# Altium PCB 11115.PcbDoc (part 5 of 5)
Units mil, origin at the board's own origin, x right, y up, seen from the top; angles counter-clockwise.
Board outline 4800 x 3500.1 mil, 4 copper layers (Top Layer, Layer 2, Layer 3, Bottom Layer), stack 61.6 mil thick; 316 components, 224 nets, 954 pads, 623 vias.
Unrouted connection lines stored in the file: 268.
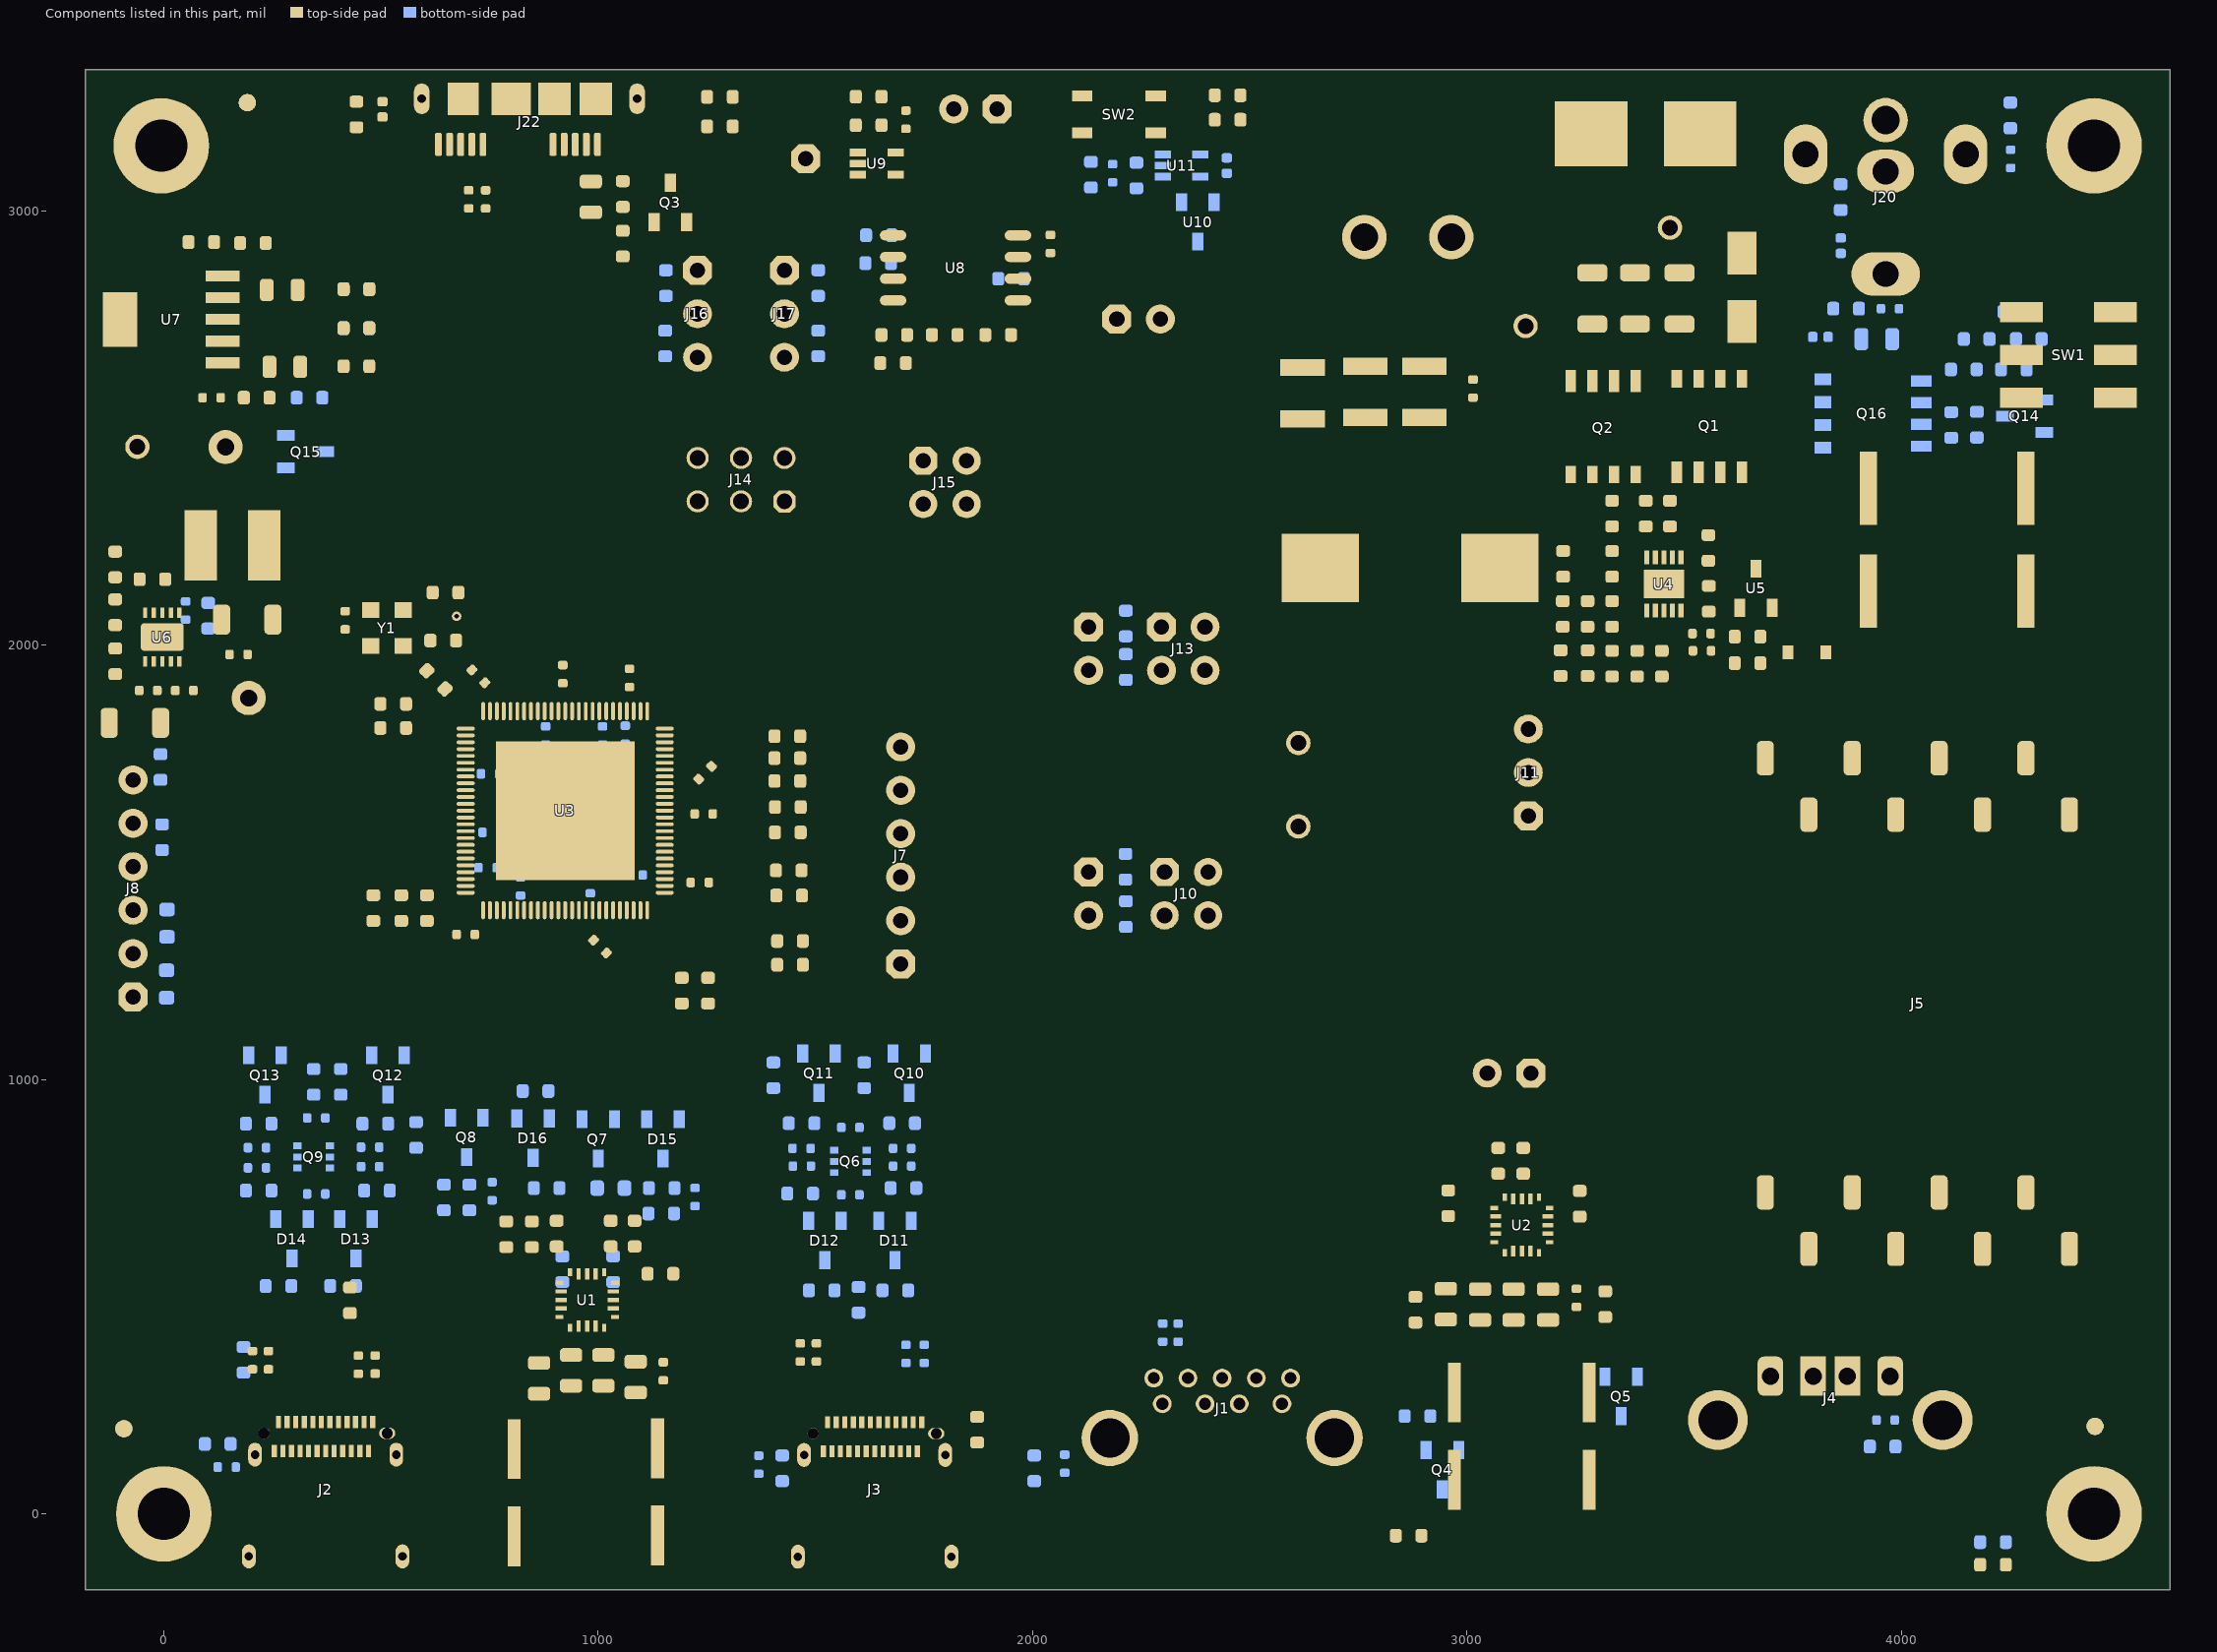
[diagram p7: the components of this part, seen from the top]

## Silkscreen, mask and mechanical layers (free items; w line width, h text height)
Top Overlay:
  circle w10: c1975.4,3285.12 r12
  circle w10: c7.55,1142.26 r12
  circle w10: c3197.78,1070.01 r12
  circle w10: c72.56,2065.34 r12
  circle w10: c677.47,1862.67 r12
  circle w10: c2244.15,1534.48 r12
  circle w10: c2068.15,1534.48 r12
  circle w10: c1764.55,1218.14 r12
  circle w10: c2239.15,2094.65 r12
  circle w10: c2135.4,2690.12 r12
  circle w10: c1689.34,2477.36 r12
  circle w10: c1486.44,2273.42 r12
  circle w10: c1355.4,2909.06 r12
  circle w10: c2072.4,2094.65 r12
  circle w10: c1160.4,2910.12 r12
  circle w10: c3209.18,1557.84 r18.03
  region: 74.15,425 74.15,1110 -130.85,1110 -130.85,425
  lines w8: -0.78,1505.87 41.96,1505.87 41.96,1572.5 -0.78,1572.5 ; 0.82,1196.05 43.56,1196.05 43.56,1262.68 0.82,1262.68 ; 0.82,1319.94 43.56,1319.94 43.56,1386.57 0.82,1386.57 ; 1.16,1607.5 43.89,1607.5 43.89,1674.13 1.16,1674.13 ; 651.44,2760 1170.72,2760 1172.66,2758.06 1172.66,2520.88 1160.4,2520.88 651.44,2520.88 651.44,2835 1024.15,2835 ; 1019.15,2835 1173.85,2835 ; 1484.08,2607.22 1546.3,2545 1948.98,2545 1948.98,2273.42 2558.37,2273.42 ; 1664.15,2200 1948.98,2200 1948.98,2191.99 1948.98,2060.17 1664.15,2060.17 1664.15,2240.63 1696.15,2272.64 ; 1806.56,2060.17 1806.56,2200 ; 1948.98,2524.42 1948.98,2585 1951.06,2587.09 2472.86,2587.09 2472.86,2385 2558.37,2385 ; 2251.79,1807.09 2251.79,1607.09 2321.15,1607.09 2378.26,1607.09 2447.62,1607.09 2447.62,1817.26 ; 2254.69,1255.92 2254.69,1023.72 2450.52,1023.72 2450.52,1266.09 ; 2819.15,1725 3009.15,1725 3008.05,1726.1 3008.05,1895 ; 3008.05,1889.92 3305.23,1889.92 3345.82,1889.92 3360.9,1905 3359.15,1905 ; 3222.15,2271 3285.15,2271 3310.15,2246 3435.15,2246 3440.15,2251 ; 3510.79,1825 3594.98,1825 3602.85,1825 3602.85,1918.44 3564.72,1957.21
  lines w10: 2727.75,2796.73 2799.75,2796.73 ; 2921.57,2795 2993.57,2795 ; 2958.42,2755 2958.42,2827
  lines w11: -155.85,2360 -155.85,2118.13 -146.46,2108.73 -146.46,2109.4
  text "\"SPI\"" at 1468.26,3265 h60
  text "\"VBUS\"" at 1331.53,3204.56 h60
  text "HOLD" at 1824.15,3109.13 h60
  text "RESET" at 2294.15,3090.63 h60
  text "GND" at 1319.15,3052.2 h60
  text "SST26VF016B" at 1745.61,3006.91 h100
  text "DC_IN" at 2581.75,2979.22 h120 r90
  text "DC_IN" at 3236.59,2941.73 h75
  text "12Vin" at 4237.26,2916.49 h120
  text "J6" at 679.97,2853.56 h60
  text "\"5V\"" at 521.7,2800.41 h60
  text "BATT CHRGING" at 689.47,2775 h60
  text "\"3V3\"" at 513.34,2714.67 h60
  text "(1-2)" at 679.97,2705 h60
  text "ALL PORTS DISABLED" at 672.67,2649.73 h60
  text "RESET" at 2179.46,2640.07 h60
  text "GND" at 3080,2635 h60
  text "\"1V1\"" at 513.34,2626.37 h60
  text "(2-3)" at 683.51,2599.35 h60
  text "ALL PORTS ENABLED" at 670.76,2541.12 h60
  text "Non-Removable" at 2072.4,2520.88 h60
  text "J7" at 1979.15,2520 h60
  text "◄ ON   OFF ►" at 4604.15,2500 h70 r90
  text "SELECT" at 2072.4,2465.55 h60
  text "3V3" at 207.7,2415 h60
  text "6" at 1123.32,2415 h60
  text "4" at 1505.35,2410 h60
  text "(1-2)" at 1964.15,2375 h60
  text "ALL REMOVABLE" at 2076,2375 h60
  text "GND" at -9.82,2369.83 h60
  text "(2-3)" at 1964.15,2310 h60
  text "ALL NON-REMOVABLE" at 2076,2310 h60
  text "3" at 1123.32,2305 h60
  text "STRAP" at 1132.45,2190.4 h60
  text "SPI" at 1389.99,2190.4 h60
  text "[1-2]" at 1373.85,2141.88 h60
  text "PF24" at 1689.34,2141.88 h60
  text "PF22" at 1824.15,2141.88 h60
  text "[2-3]" at 1160.4,2131.54 h60
  text "CLK/PF31" at 2244.78,2120 h60
  text "[4-5]" at 1373.85,2080.12 h60
  text "PF25" at 1692.09,2080.12 h60
  text "PF21" at 1824.15,2080.12 h60
  text "[5-6]" at 1160.4,2073.33 h60
  text "P/U ENABLE" at 2035,1855 h60 r90
  text "VCORE" at 264.64,1835.67 h60
  text "DATA/PF30" at 2244.15,1830 h60
  text "5V" at 4302.22,1825 h60 r90
  text "SCL" at 4107.22,1815 h60 r90
  text "DAT" at 4207.22,1815 h60 r90
  text "GND" at 4412.7,1815 h60 r90
  text "SPR1" at 3707.22,1795 h60 r90
  text "SPR2" at 3905.94,1795 h60 r90
  text "SPR3" at 4007.05,1795 h60 r90
  text "MIC DET" at 3805.22,1790 h55 r90
  text "SPARE3" at 3222.15,1780 h60
  text "PF29" at 1769.15,1745 h60
  text "5V" at 2687.53,1721.69 h60
  text "USB7252" at 335,1695.42 h100
  text "SPARE2" at 3224.15,1685 h60
  text "PF18" at 1769.05,1649.54 h60
  text "CFG1*" at 67.46,1619.13 h60
  text "5-6" at 205.59,1619.13 h60
  text "SPARE1" at 3227.21,1600 h60
  text "SMB/I2C MSTR" at 2215,1562.8 h60 r90
  text "GND" at 2687.53,1557.84 h60
  text "CLK/PF26" at 2244.78,1553.14 h60
  text "PF12" at 1774.15,1540 h60
  text "CFG2" at 67.46,1522.5 h60
  text "4-5" at 205.59,1522.5 h60
  text "PF9" at 1774.15,1449.6 h60
  text "PF8" at 1770.45,1345 h60
  text "CFG3" at 69.43,1334 h60
  text "2-3" at 205.59,1334 h60
  text "P/U ENABLE" at 2035,1297.06 h60 r90
  text "DATA/PF19" at 2245,1275 h60
  text "PF6" at 1770.45,1255.99 h60
  text "CFG4" at 69.43,1220 h60
  text "1-2" at 205.59,1220 h60
  text "C" at 3807.22,1105 h350
  text "e" at 3434.15,1075 h300
  text "SMB/I2C SLAVE" at 2210,959.88 h60 r90
  text "M" at 475.94,910 h400
  text "EVB USB7252" at 482.45,780 h150
  text "" at 2604.15,745 h400
  text "04-11115-R1.1" at 175,675 h100 r90
  text "" at 2285,608.9 h450
  text "UCS2114" at 2649.15,565 h120
  text "PORT 1" at 94.15,465.65 h100
  text "3V3" at 4312.22,460 h60 r90
  text "SDI" at 3907.22,450.92 h60 r90
  text "SDO" at 4007.22,450.92 h60 r90
  text "SCK" at 4205.22,450 h60 r90
  text "GND" at 4409.15,450 h60 r90
  text "UCS2114" at 491.65,436.59 h120
  text "USB3" at 2449.15,433.89 h100
  text "MCLK" at 3714.15,425 h60 r90
  text "USB3" at 114.15,415 h100
  text "RESET" at 3807.22,415 h60 r90
  text "LRCLK" at 4095.31,415 h60 r90
  text "PORT 3" at 2139.15,396.78 h100
  text "PORT 2" at 1610,354 h100
  text "USB2.0" at 4185,345 h100
  text "USB3" at 1623,296 h100
  text "S/N" at 42,268 h120 r90
  text "PORT 4" at 4190,267.92 h100
  text "\"P4 / VBUS\"" at 4152.22,-25 h60
  text ".Layer_Name" at 1171.6,-360 h100
  text ".Layer_Name" at 11420.01,-4182.53 h59.06
  text ".ProjectRevisionART" at 12774.96,-4185.53 h59.06
Bottom Overlay:
  lines w11: 525.72,826.57 526.39,826.57 558.9,794.05 558.9,611.39 569.15,601.15 ; 547.42,926.73 546.95,926.73 611.9,991.69 611.9,1003.03 ; 1394.15,940.2 1474.05,940.2
  text ".Layer_Name" at 1171.6,-375 h110
  text ".Layer_Name" at 11420.01,-4182.53 h59.06
  text ".ProjectRevisionART" at 12774.96,-4185.53 h59.06
Top Paste:
  text ".Layer_Name" at 11420.01,-4182.53 h59.06
  text ".ProjectRevisionART" at 12774.96,-4185.53 h59.06
Bottom Paste:
  text ".Layer_Name" at 11420.01,-4182.53 h59.06
  text ".ProjectRevisionART" at 12774.96,-4185.53 h59.06
Top Solder:
  rectangle: 3407.82,2065.32 3498.44,2095
  rectangle: 3407.82,2187.5 3498.44,2216.95
  rectangle: 889.66,3126.3 1007.5,3180.78
  rectangle: 622.5,3127.5 741,3178.1
  text ".Layer_Name" at 1156.6,-380 h110
  text ".Layer_Name" at 11420.01,-4182.53 h59.06
  text ".ProjectRevisionART" at 12774.96,-4185.53 h59.06
Bottom Solder:
  region: 4440.98,1470 4440.98,870 4566.85,870 4566.85,1470
  text ".Layer_Name" at 1161.6,-375 h110
  text ".Layer_Name" at 11420.01,-4182.53 h59.06
  text ".ProjectRevisionART" at 12774.96,-4185.53 h59.06
Drill Guide:
  text ".Layer_Name" at 11435,-4182.5 h59.06
NOTES (M1):
  text ".Layer_Name" at 12128.67,-4182.53 h59.06
BOARD (M2):
  lines w5: -180.85,3325 4619.15,3325 4619.15,-175 -180.85,-175 -180.85,3325.1
REF POINTS (M3):
  text ".Layer_Name" at 11420.01,-4182.53 h59.06
Case (M5):
  text ".Layer_Name" at 11420.01,-4182.53 h59.06
Cover (M6):
  text ".Layer_Name" at 11420.01,-4182.53 h59.06
Terminal Block (M7):
  text ".Layer_Name" at 11420.01,-4182.53 h59.06
Route Tool Path:
  text ".Layer_Name" at 11420.01,-4182.53 h59.06
V-Cut (M9):
  text ".Layer_Name" at 11420.01,-4182.53 h59.06
Bottom Assy TOP (M11)/Assy BOT (M10):
  text ".variantName" at 1560.56,-3552.6 h35.43
  text "ASSEMBLY VARIANT:" at 2121.58,-3552.61 h35.43
  text "DOCUMENT NUMBER:" at 299.93,-3877.41 h45
  text "-D" at -251.25,-3995.52 h70
  text ".ProjectBoardNumber" at 73.55,-3995.52 h70
  text "02-" at 290.09,-3995.52 h70
  text ".ProjectRevisionASSY" at -366.52,-4175.53 h59.06
  text ".Layer_Name" at 1006.62,-4182.53 h40
Top Assy TOP (M11)/Assy BOT (M10):
  text "Assembly: NOTE UNLESS OTHERWISE SPECIFIED:" at 4817.3,3894 h150
  text "1. ALL COMPONENTS SHALL BE RoHS COMPLIANT." at 4854.3,3594 h150
  text "2. ALL UNUSED THROUGH HOLE COMPONENT LOCATIONS SHALL BE FREE OF SOLDER." at 4854.3,3414 h150
  text "3. ALL COMPONENTS SHALL BE MOUNTED FLUSH TO THE BOARD, EXCEPT AS NOTED." at 4854.3,3234 h150
  text "4. FINISHED BOARD SHALL BE FREE OF ALL RESIDUES." at 4854.3,3054 h150
  text "5. PLACE SERIAL NUMBER LABEL INSIDE \"S/N\" BOX ON TOP SIDE SILK." at 4854.3,2874 h150
  text "6. WORKMANSHIP TO BE COMPLIANT WITH THE IPC-A-610, CLASS 2." at 4854.3,2687.38 h150
  text "7. THIS ASSEMBLY CONTAINS ELECTROSTATIC DISCHARGE (ESD) DEVICES;" at 4854.3,2527.38 h150
  text "STATIC-FREE HANDLING IS REQUIRED." at 5014.3,2367.38 h150
  text "ASSEMBLY VARIANT:" at 10317.65,-3552.61 h35.43
  text ".variantName" at 10878.67,-3552.61 h35.43
  text "DOCUMENT NUMBER:" at 12138.51,-3877.41 h45
  text "02-" at 12148.36,-3995.52 h70
  text ".ProjectBoardNumber" at 12364.89,-3995.52 h70
  text "-D" at 12689.69,-3995.52 h70
  text ".Layer_Name" at 11420.01,-4182.53 h45
  text ".ProjectRevisionASSY" at 12774.96,-4185.53 h59.06
Bottom 3D TOP (M13)/3D BOT (M12):
  text ".Layer_Name" at 11420.01,-4182.53 h45
Top 3D TOP (M13)/3D BOT (M12):
  text ".Layer_Name" at 11420.01,-4182.53 h45
Bottom Guard TOP (M15)/Guard BOT (M14):
  text ".Layer_Name" at 11420.01,-4182.53 h38
  text ".ProjectRevisionART" at 12774.96,-4185.53 h59.06
Top Guard TOP (M15)/Guard BOT (M14):
  text ".Layer_Name" at 11420.01,-4182.53 h40
  text ".ProjectRevisionART" at 12774.96,-4185.53 h59.06
TITLE (M16):
  lines w3.94: 10297.96,-3503.39 13519.22,-3503.39 ; 12542.06,-3208.12 12542.06,-3326.23 13519.22,-3326.23 ; 13075.13,-4178 13075.13,-4128 ; 13075.13,-4153 13475.13,-4153 ; 13081.43,-4105.75 13081.43,-4066.38 ; 13081.43,-4086.07 13475.13,-4086.07 ; 13175.13,-4178 13175.13,-4128 ; 13275.13,-4178 13275.13,-4128 ; 13278.28,-4097.88 13278.28,-4074.26 ; 13375.13,-4178 13375.13,-4128 ; 13475.13,-4178 13475.13,-4128 ; 13475.13,-4105.75 13475.13,-4066.38 ; 13519.22,-3326.23 13519.22,-3326.23
  lines w5: -1280.78,-2033.9 -1080.78,-2033.9 ; -1280.78,341.1 -1080.78,341.1 ; -1280.78,2716.1 -1080.78,2716.1 ; 1219.22,-4408.9 1219.22,-4208.9 ; 1219.22,4891.1 1219.22,5091.1 ; 3719.22,-4408.9 3719.22,-4208.9 ; 3719.22,4891.1 3719.22,5091.1 ; 6219.22,-4408.9 6219.22,-4208.9 ; 6219.22,4891.1 6219.22,5091.1 ; 7619.22,-4208.9 9019.22,-4208.9 ; 8719.22,-4408.9 8719.22,-4208.9 ; 8719.22,4891.1 8719.22,5091.1 ; 8959.38,-4208.9 8959.38,-3208.12 13519.22,-3208.12 ; 10297.96,-4208.9 10297.96,-3208.12 ; 10297.96,-4034.89 13519.22,-4034.89 ; 10297.96,-3798.67 13519.22,-3798.67 ; 10297.96,-3562.45 13519.22,-3562.45 ; 11219.22,-4408.9 11219.22,-4208.9 ; 11219.22,4891.1 11219.22,5091.1 ; 11400.32,-4208.9 11400.32,-3562.45 ; 12108.99,-4034.89 12108.99,-3798.67 ; 12620.8,-4208.9 12620.8,-4034.89 ; 12916.07,-4208.9 12916.07,-3798.67 ; 13519.22,-3008.9 13519.22,-4208.9 ; 13519.22,-2033.9 13719.22,-2033.9 ; 13519.22,341.1 13719.22,341.1 ; 13519.22,2716.1 13719.22,2716.1 ; 13519.22,-4208.9 -1080.78,-4208.9 -1080.78,4891.1 13519.22,4891.1 13519.22,-4208.9 ; -1280.78,-4408.9 13719.22,-4408.9 13719.22,5091.1 -1280.78,5091.1 -1280.78,-4408.9
  lines w10: 8723.16,4882.43 8723.16,4705.27 ; 9156.23,4528.1 9156.23,4705.27 9156.23,4882.43 ; 9648.36,4528.1 9648.36,4705.27 9648.36,4882.43 ; 12738.91,4528.1 12738.91,4705.27 12738.91,4882.43 ; 13506.62,4528.1 8723.16,4528.1 8723.16,4705.27 ; 13506.62,4705.27 8723.16,4705.27
  text "1" at -49.44,4961.1 h70
  text "2" at 2446.22,4961.1 h70
  text "3" at 4935.56,4961.1 h70
  text "4" at 7442.23,4961.1 h70
  text "5" at 9941.22,4961.1 h70
  text "6" at 12446.22,4961.1 h70
  text "REV" at 8821.58,4764.32 h60
  text "ECO" at 9215.28,4764.32 h60
  text "Comments" at 11045.99,4744.64 h60
  text "Date" at 12935.76,4744.64 h60
  text "A" at -1205.78,3818.1 h70
  text "A" at 13594.22,3818.1 h70
  text "B" at -1205.78,1438.1 h70
  text "B" at 13594.22,1438.1 h70
  text "C" at -1205.78,-936.9 h70
  text "C" at 13594.22,-936.9 h70
  text "PART NUMBER:" at 12581.43,-3286.86 h39.37
  text ".ProjectpartNumber" at 13030.3,-3299 h50
  text "D" at -1205.78,-3306.9 h70
  text "TITLE:" at 10337.33,-3306.54 h45
  text "D" at 13594.22,-3306.9 h70
  text ".ProjectTitle" at 10337.33,-3464.02 h98.43
  text "PCB DESIGNER:" at 10337.33,-3641.19 h45
  text "GERBER FILE:" at 11439.69,-3641.19 h45
  text ".ProjectDrawnBy" at 10337.33,-3759.3 h70
  text ".Plot_File_Name" at 11439.69,-3759.3 h59.06
  text "M" at 9077.49,-3838.04 h600
  text "ENGINEER:" at 10337.33,-3877.41 h45
  text "BOARD NUMBER:" at 11439.69,-3877.41 h45
  text "DATE:" at 12963.32,-3877.41 h45
  text "Microchip Technology Inc." at 9029.06,-3966.38 h70
  text ".ProjectEngineer" at 10337.33,-3995.52 h70
  text "04-" at 11439.69,-3995.52 h55
  text ".ProjectBoardNumber" at 11636.54,-3995.52 h55
  text ".PRINT_DATE" at 12963.32,-3995.52 h59.06
  text "2355 W. Chandler Blvd." at 9077.49,-4074.26 h70
  text "LAYER NAME:" at 11439.69,-4093.94 h45
  text "10mm" at 12935.76,-4097.88 h27.56
  text "PCB FILE NAME:" at 10337.33,-4103.79 h45
  text "REV:" at 12650.32,-4103.79 h45
  text "400mil" at 12931.82,-4164.81 h27.56
  text "Chandler, AZ  85224" at 9116.86,-4172.68 h70
  text ".PCB_FILE_NAME_NO_PATH" at 10337.33,-4182.53 h45
  text "1" at -49.44,-4338.9 h70
  text "2" at 2446.22,-4338.9 h70
  text "3" at 4935.56,-4338.9 h70
  text "4" at 7442.23,-4338.9 h70
  text "5" at 9941.22,-4338.9 h70
  text "6" at 12446.22,-4338.9 h70
Drill Drawing:
  drawing of 444 lines, arcs and shapes, not listed
  text "NOTE UNLESS OTHERWISE SPECIFIED:" at 8251.58,3849.98 h150
  text "1.  Base Material 370HR, Rohs compliant and compatible." at 8251.58,3674.98 h150
  text "2.  PCB thickness: 0.062, +/- 0.007\" finished." at 8251.58,3499.98 h150
  text "3.  PCB Construction: 4 layers." at 8247.74,3275.64 h150
  text "This construction shall be as detailed per Layer Stackup Table." at 8401.58,3124.98 h150
  text "4. Conductive Pattern finish: IPC ENIG (Au over Ni)." at 8255.24,2960.64 h150
  text "5. Soldermask: Soldermask over bare copper, \"BLUE\", both sides." at 8255.24,2810.64 h150
  text "Soldermask shall be in accordance with IPC-SM-840 Class T." at 8405.24,2660.64 h150
  text "There shall be no soldermask on any land." at 8405.24,2510.64 h150
  text "6. Silkscreen: DO NOT clear silkscreen from tented vias." at 8255.64,2316.82 h150
  text "White, permanent, non-conductive ink: Applied to both sides." at 8405.24,2160.64 h150
  text "There shall be no ink on any exposed land." at 8405.24,2010.64 h150
  text "7. Board fabrication acceptance shall meet IPC-6012B Class 2 workmanship requirements." at 8255.24,1810.64 h150
  text "8. Minimum copper plate in all holes to be 0.001 inches." at 8255.24,1610.64 h150
  text "9. Copper thieving may be added by the PCB fabricator on inner and outer layers" at 8260.24,1433.14 h150
  text "to assist the plating process ONLY IF:" at 8260.24,1283.14 h150
  text "A. All thieving pads are kept at least 55 mils from other features." at 8435.24,1109.64 h150
  text "B. The thieving pattern is made up of individual and separate pads." at 8435.24,959.64 h150
  text "(No hatching or grid lines.)" at 8405.24,794.64 h150
  text "10. PCB must be tested per IPC-9252 Class 2. Any diviation from this" at 8254.08,609.98 h150
  text "requirement must have written authorization from Microchip Technology Inc." at 8435.24,459.64 h150
  text "11.  Vendor ID, UL rating, date code and/or lot number must appear on this board in" at 8257.74,262.14 h150
  text "copper located as shown on bottom side." at 8464.08,127.48 h150
  text "Written in silk acceptable." at 10461.3,125 h150
  text "12. Finished drill hole size tolerances unless otherwise specified;" at 8257.74,-95.36 h150
  text "Under 0.021 inches: +0.003/ -0.006" at 8457.74,-245.36 h150
  text "0.021 to 0.090 inches: +/- 0.003" at 8457.74,-395.36 h150
  text "Over 0.090 inches: +/- 0.006" at 8457.74,-545.36 h150
  text "Symbol" at -357.5,-561.06 h72
  text "Count" at 148.38,-561.06 h72
  text "Hole Size" at 748.22,-561.06 h72
  text "Plated" at 1897.88,-561.06 h72
  text "Hole Type" at 2403.76,-561.06 h72
  text "Drill Layer Pair" at 3137.56,-561.06 h72
  text "Via/Pad" at 4637.11,-561.06 h72
  text "Hole Length" at 5226.96,-561.06 h72
  text "Routed Path Length" at 6346.63,-561.06 h72
  text "1" at 148.38,-711.06 h60
  text "60.00mil (1.524mm)" at 748.22,-711.06 h60
  text "PTH" at 1897.88,-711.06 h60
  text "Slot" at 2403.76,-711.06 h60
  text "Top Layer - Bottom Layer" at 3137.56,-711.06 h60
  text "Pad" at 4637.11,-711.06 h60
  text "90.55mil (2.300mm)" at 5226.96,-711.06 h60
  text "30.55mil (0.776mm)" at 6346.63,-711.06 h60
  text "E" at -386.59,-721.05 h66.67
  text "13. Traces shall finish at the artwork width, +/- 1 mil." at 8259.08,-747.52 h150
  text "1" at 148.38,-861.06 h60
  text "60.00mil (1.524mm)" at 748.22,-861.06 h60
  text "PTH" at 1897.88,-861.06 h60
  text "Slot" at 2403.76,-861.06 h60
  text "Top Layer - Bottom Layer" at 3137.56,-861.06 h60
  text "Pad" at 4637.11,-861.06 h60
  text "118.11mil (3.000mm)" at 5226.96,-861.06 h60
  text "58.11mil (1.476mm)" at 6346.63,-861.06 h60
  text "F" at -386.59,-871.05 h66.67
  text "14. Miniumum Trace and Space = 6 mil / 7 mil (ref.)" at 8259.08,-922.52 h150
  text "1" at 148.38,-1011.06 h60
  text "65.47mil (1.663mm)" at 748.22,-1011.06 h60
  text "PTH" at 1897.88,-1011.06 h60
  text "Round" at 2403.76,-1011.06 h60
  text "Top Layer - Bottom Layer" at 3137.56,-1011.06 h60
  text "Pad" at 4637.11,-1011.06 h60
  text "-" at 5226.96,-1011.06 h60
  text "-" at 6346.63,-1011.06 h60
  text "G" at -386.59,-1021.05 h66.67
  text "2" at 148.38,-1161.06 h60
  text "19.69mil (0.500mm)" at 748.22,-1161.06 h60
  text "PTH" at 1897.88,-1161.06 h60
  text "Slot" at 2403.76,-1161.06 h60
  text "Top Layer - Bottom Layer" at 3137.56,-1161.06 h60
  text "Pad" at 4637.11,-1161.06 h60
  text "55.12mil (1.400mm)" at 5226.96,-1161.06 h60
  text "35.43mil (0.900mm)" at 6346.63,-1161.06 h60
  text "2" at 148.38,-1311.06 h60
  text "25.59mil (0.650mm)" at 748.22,-1311.06 h60
  text "NPTH" at 1897.88,-1311.06 h60
  text "Round" at 2403.76,-1311.06 h60
  text "Top Layer - Bottom Layer" at 3137.56,-1311.06 h60
  text "Pad" at 4637.11,-1311.06 h60
  text "-" at 5226.96,-1311.06 h60
  text "-" at 6346.63,-1311.06 h60
  text "+/-10%, ref to L1/GND." at 11826,-1335 h150
  text "2" at 148.38,-1461.06 h60
  text "25.59mil (0.650mm)" at 748.22,-1461.06 h60
  text "NPTH" at 1897.88,-1461.06 h60
  text "Slot" at 2403.76,-1461.06 h60
  text "Top Layer - Bottom Layer" at 3137.56,-1461.06 h60
  text "Pad" at 4637.11,-1461.06 h60
  text "37.40mil (0.950mm)" at 5226.96,-1461.06 h60
  text "11.81mil (0.300mm)" at 6346.63,-1461.06 h60
  text "+/-10%, ref to L4/PWR." at 12088,-1518 h150
  text "2" at 148.38,-1611.06 h60
  text "60.00mil (1.524mm)" at 748.22,-1611.06 h60
  text "PTH" at 1897.88,-1611.06 h60
  text "Slot" at 2403.76,-1611.06 h60
  text "Top Layer - Bottom Layer" at 3137.56,-1611.06 h60
  text "Pad" at 4637.11,-1611.06 h60
  text "98.43mil (2.500mm)" at 5226.96,-1611.06 h60
  text "38.43mil (0.976mm)" at 6346.63,-1611.06 h60
  text "D" at -386.59,-1621.05 h66.67
  text "2" at 148.38,-1761.06 h60
  text "62.99mil (1.600mm)" at 748.22,-1761.06 h60
  text "PTH" at 1897.88,-1761.06 h60
  text "Round" at 2403.76,-1761.06 h60
  text "Top Layer - Bottom Layer" at 3137.56,-1761.06 h60
  text "Pad" at 4637.11,-1761.06 h60
  text "-" at 5226.96,-1761.06 h60
  text "-" at 6346.63,-1761.06 h60
  text "Layer" at 8068.96,-1775 h60
  text "Name" at 8478.88,-1775 h60
  text "Material" at 9408.62,-1775 h60
  text "Thickness" at 10958.16,-1775 h60
  text "Constant" at 11608,-1775 h60
  text "Board Layer Stack" at 12177.86,-1775 h60
  text "Top Overlay" at 8478.88,-1895 h60
  text "4" at 148.38,-1911.06 h60
  text "11.81mil (0.300mm)" at 748.22,-1911.06 h60
  text "PTH" at 1897.88,-1911.06 h60
  text "Round" at 2403.76,-1911.06 h60
  text "Top Layer - Bottom Layer" at 3137.56,-1911.06 h60
  text "Via" at 4637.11,-1911.06 h60
  text "-" at 5226.96,-1911.06 h60
  text "-" at 6346.63,-1911.06 h60
  text "B" at -386.59,-1921.05 h66.67
  text "Top Solder" at 8478.88,-2015 h60
  text "Solder Resist" at 9408.62,-2015 h60
  text "0.40mil" at 10958.16,-2015 h60
  text "3.5" at 11608,-2015 h60
  text "4" at 148.38,-2061.06 h60
  text "90.55mil (2.300mm)" at 748.22,-2061.06 h60
  text "PTH" at 1897.88,-2061.06 h60
  text "Round" at 2403.76,-2061.06 h60
  text "Top Layer - Bottom Layer" at 3137.56,-2061.06 h60
  text "Pad" at 4637.11,-2061.06 h60
  text "-" at 5226.96,-2061.06 h60
  text "-" at 6346.63,-2061.06 h60
  text "1" at 8068.96,-2135 h60
  text "Top Layer" at 8478.88,-2135 h60
  text "Copper" at 9408.62,-2135 h60
  text "1.40mil" at 10958.16,-2135 h60
  text "4" at 148.38,-2211.06 h60
  text "120.00mil (3.048mm)" at 748.22,-2211.06 h60
  text "PTH" at 1897.88,-2211.06 h60
  text "Round" at 2403.76,-2211.06 h60
  text "Top Layer - Bottom Layer" at 3137.56,-2211.06 h60
  text "Pad" at 4637.11,-2211.06 h60
  text "-" at 5226.96,-2211.06 h60
  text "-" at 6346.63,-2211.06 h60
  text "Dielectric 1" at 8478.88,-2255 h60
  text "370HR(1PLY 1080&1PLY 106)" at 9408.62,-2255 h60
  text "4.50mil" at 10958.16,-2255 h60
  text "4.2" at 11608,-2255 h60
  text "6" at 148.38,-2361.06 h60
  text "39.37mil (1.000mm)" at 748.22,-2361.06 h60
  text "PTH" at 1897.88,-2361.06 h60
  text "Round" at 2403.76,-2361.06 h60
  text "Top Layer - Bottom Layer" at 3137.56,-2361.06 h60
  text "Pad" at 4637.11,-2361.06 h60
  text "-" at 5226.96,-2361.06 h60
  text "-" at 6346.63,-2361.06 h60
  text "2" at 8068.96,-2375 h60
  text "Layer 2" at 8478.88,-2375 h60
  text "Copper" at 9408.62,-2375 h60
  text "1.40mil" at 10958.16,-2375 h60
  text "Dielectric 2" at 8478.88,-2495 h60
  text "370 HR" at 9408.62,-2495 h60
  text "47.00mil" at 10958.16,-2495 h60
  text "4.3" at 11608,-2495 h60
  text "7" at 148.38,-2511.06 h60
  text "12.00mil (0.305mm)" at 748.22,-2511.06 h60
  text "PTH" at 1897.88,-2511.06 h60
  text "Round" at 2403.76,-2511.06 h60
  text "Top Layer - Bottom Layer" at 3137.56,-2511.06 h60
  text "Via" at 4637.11,-2511.06 h60
  text "-" at 5226.96,-2511.06 h60
  text "-" at 6346.63,-2511.06 h60
  text "A" at -386.59,-2521.05 h66.67
  text "3" at 8068.96,-2615 h60
  text "Layer 3" at 8478.88,-2615 h60
  text "Copper" at 9408.62,-2615 h60
  text "1.40mil" at 10958.16,-2615 h60
  text "8" at 148.38,-2661.06 h60
  text "19.69mil (0.500mm)" at 748.22,-2661.06 h60
  text "PTH" at 1897.88,-2661.06 h60
  text "Slot" at 2403.76,-2661.06 h60
  text "Top Layer - Bottom Layer" at 3137.56,-2661.06 h60
  text "Pad" at 4637.11,-2661.06 h60
  text "43.31mil (1.100mm)" at 5226.96,-2661.06 h60
  text "23.62mil (0.600mm)" at 6346.63,-2661.06 h60
  text "H" at -386.59,-2671.05 h66.67
  text "Dielectric 3" at 8478.88,-2735 h60
  text "370HR(1PLY 1080&1PLY 106)" at 9408.62,-2735 h60
  text "4.50mil" at 10958.16,-2735 h60
  text "4.8" at 11608,-2735 h60
  text "9" at 148.38,-2811.06 h60
  text "27.56mil (0.700mm)" at 748.22,-2811.06 h60
  text "PTH" at 1897.88,-2811.06 h60
  text "Round" at 2403.76,-2811.06 h60
  text "Top Layer - Bottom Layer" at 3137.56,-2811.06 h60
  text "Pad" at 4637.11,-2811.06 h60
  text "-" at 5226.96,-2811.06 h60
  text "-" at 6346.63,-2811.06 h60
  text "4" at 8068.96,-2855 h60
  text "Bottom Layer" at 8478.88,-2855 h60
  text "Copper" at 9408.62,-2855 h60
  text "1.40mil" at 10958.16,-2855 h60
  text "11" at 148.38,-2961.06 h60
  text "36.00mil (0.914mm)" at 748.22,-2961.06 h60
  text "PTH" at 1897.88,-2961.06 h60
  text "Round" at 2403.76,-2961.06 h60
  text "Top Layer - Bottom Layer" at 3137.56,-2961.06 h60
  text "Pad" at 4637.11,-2961.06 h60
  text "-" at 5226.96,-2961.06 h60
  text "-" at 6346.63,-2961.06 h60
  text "Bottom Solder" at 8478.88,-2975 h60
  text "Solder Resist" at 9408.62,-2975 h60
  text "0.39mil" at 10958.16,-2975 h60
  text "3.5" at 11608,-2975 h60
  text "Bottom Overlay" at 8478.88,-3095 h60
  text "37" at 148.38,-3111.06 h60
  text "11.00mil (0.279mm)" at 748.22,-3111.06 h60
  text "PTH" at 1897.88,-3111.06 h60
  text "Round" at 2403.76,-3111.06 h60
  text "Top Layer - Bottom Layer" at 3137.56,-3111.06 h60
  text "(Mixed)" at 4637.11,-3111.06 h60
  text "-" at 5226.96,-3111.06 h60
  text "-" at 6346.63,-3111.06 h60
  text "C" at -386.59,-3121.05 h66.67
  text "44" at 148.38,-3261.06 h60
  text "35.43mil (0.900mm)" at 748.22,-3261.06 h60
  text "PTH" at 1897.88,-3261.06 h60
  text "Round" at 2403.76,-3261.06 h60
  text "Top Layer - Bottom Layer" at 3137.56,-3261.06 h60
  text "Pad" at 4637.11,-3261.06 h60
  text "-" at 5226.96,-3261.06 h60
  text "-" at 6346.63,-3261.06 h60
  text "88" at 148.38,-3411.06 h60
  text "10.00mil (0.254mm)" at 748.22,-3411.06 h60
  text "PTH" at 1897.88,-3411.06 h60
  text "Round" at 2403.76,-3411.06 h60
  text "Top Layer - Bottom Layer" at 3137.56,-3411.06 h60
  text "Via" at 4637.11,-3411.06 h60
  text "-" at 5226.96,-3411.06 h60
  text "-" at 6346.63,-3411.06 h60
  text "488" at 148.38,-3561.06 h60
  text "10.00mil (0.254mm)" at 748.22,-3561.06 h60
  text "PTH" at 1897.88,-3561.06 h60
  text "Round" at 2403.76,-3561.06 h60
  text "Top Layer - Bottom Layer" at 3137.56,-3561.06 h60
  text "Via" at 4637.11,-3561.06 h60
  text "-" at 5226.96,-3561.06 h60
  text "-" at 6346.63,-3561.06 h60
  text "723 Total" at 148.38,-3711.06 h60
  text "Slot definitions :" at -357.5,-3856.03 h60
  text "Routed Path Length" at 675.19,-3856.03 h60
  text "= Calculated from tool start centre position to tool end centre position." at 1777.86,-3856.03 h60
  text "DOCUMENT NUMBER:" at 12138.51,-3877.41 h45
  text "Hole Length" at 675.19,-3956.01 h60
  text "= Routed Path Length + Tool Size = Slot length as defined in the PCB layout" at 1367.99,-3956.01 h60
  text ".ProjectBoardNumber" at 12420,-3990 h55
  text "04-" at 12148.36,-3995.52 h70
  text "-D" at 12789.3,-3995.52 h55
  text ".Layer_Name" at 11430,-4182.53 h59.06
  text ".ProjectRevisionFAB" at 12774.96,-4185.53 h59.06
  text ".ProjectRevisionFAB" at 12774.96,-4185.53 h59.06
TITLE MIRROR (M17):
  lines w3.94: -1079.99,-3503.39 2141.27,-3503.39 ; -1036.68,-4178 -1036.68,-4128 ; -1036.68,-4153 -636.68,-4153 ; -1036.68,-4105.75 -1036.68,-4066.38 ; -1036.68,-4086.07 -642.98,-4086.07 ; -936.68,-4178 -936.68,-4128 ; -839.83,-4097.88 -839.83,-4074.26 ; -836.68,-4178 -836.68,-4128 ; -736.68,-4178 -736.68,-4128 ; -642.98,-4105.75 -642.98,-4066.38 ; -636.68,-4178 -636.68,-4128 ; -102.83,-3208.12 -102.83,-3326.23 -1079.99,-3326.23 ; -1079.99,-3326.23 -1079.99,-3326.23
  lines w5: -1280.78,-2033.9 -1080.78,-2033.9 ; -1280.78,341.1 -1080.78,341.1 ; -1280.78,2716.1 -1080.78,2716.1 ; -1080.78,-4034.89 2140.48,-4034.89 ; -1080.78,-3798.67 2140.48,-3798.67 ; -1079.99,-3562.45 2141.27,-3562.45 ; -1079.99,-3208.12 3479.85,-3208.12 3479.85,-4208.9 ; -477.63,-4208.9 -477.63,-3798.67 ; -182.35,-4208.9 -182.35,-4034.89 ; 329.46,-4034.89 329.46,-3798.67 ; 1038.91,-4208.9 1038.91,-3562.45 ; 1219.22,-4408.9 1219.22,-4208.9 ; 1219.22,4891.1 1219.22,5091.1 ; 2141.27,-4208.9 2141.27,-3208.12 ; 3719.22,-4408.9 3719.22,-4208.9 ; 3719.22,4891.1 3719.22,5091.1 ; 6219.22,-4408.9 6219.22,-4208.9 ; 6219.22,4891.1 6219.22,5091.1 ; 8719.22,-4408.9 8719.22,-4208.9 ; 8719.22,4891.1 8719.22,5091.1 ; 11219.22,-4408.9 11219.22,-4208.9 ; 11219.22,4891.1 11219.22,5091.1 ; 13519.22,-2033.9 13719.22,-2033.9 ; 13519.22,341.1 13719.22,341.1 ; 13519.22,2716.1 13719.22,2716.1 ; -1280.78,-4408.9 -1280.78,5091.1 13719.22,5091.1 13719.22,-4408.9 -1280.78,-4408.9 ; -1080.78,-4208.9 -1080.78,4891.1 13519.22,4891.1 13519.22,-4208.9 -1080.78,-4208.9
  text "6" at -7.78,4961.1 h70
  text "5" at 2497.22,4961.1 h70
  text "4" at 4996.21,4961.1 h70
  text "3" at 7502.88,4961.1 h70
  text "2" at 9992.22,4961.1 h70
  text "1" at 12487.88,4961.1 h70
  text "A" at -1155.78,3818.1 h70
  text "A" at 13644.22,3818.1 h70
  text "B" at -1155.78,1438.1 h70
  text "B" at 13644.22,1438.1 h70
  text "C" at -1155.78,-936.9 h70
  text "C" at 13644.22,-936.9 h70
  text "PART NUMBER:" at -142.2,-3286.86 h39.37
  text "TITLE:" at 2101.9,-3286.86 h45
  text ".ProjectpartNumber" at -614.64,-3296.7 h59.06
  text "D" at -1155.78,-3306.9 h70
  text "D" at 13644.22,-3306.9 h70
  text ".ProjectTitle" at 2101.9,-3464.02 h98.43
  text "GERBER FILE:" at 999.54,-3641.19 h45
  text "PCB DESIGNER:" at 2101.9,-3641.19 h45
  text ".Plot_File_Name" at 999.54,-3759.3 h59.06
  text ".ProjectDrawnBy" at 2101.9,-3759.3 h70
  text "M" at 3361.74,-3838.04 h600
  text "DATE:" at -524.87,-3877.41 h45
  text "BOARD NUMBER:" at 998.75,-3877.41 h45
  text "ENGINEER:" at 2101.11,-3877.41 h45
  text "Microchip Technology Inc." at 3410.17,-3966.38 h70
  text ".PRINT_DATE" at -524.87,-3995.52 h59.06
  text ".ProjectBoardNumber" at 801.9,-3995.52 h70
  text "04-" at 998.75,-3995.52 h70
  text ".ProjectEngineer" at 2101.11,-3995.52 h70
  text "2355 W. Chandler Blvd." at 3361.74,-4074.26 h70
  text "LAYER NAME:" at 998.75,-4093.94 h45
  text "10mm" at -497.31,-4097.88 h27.56
  text "REV:" at -211.88,-4103.79 h45
  text "PCB FILE NAME:" at 2101.11,-4103.79 h45
  text "400mil" at -493.38,-4164.81 h27.56
  text "Chandler, AZ  85224" at 3322.37,-4172.68 h70
  text ".PCB_FILE_NAME_NO_PATH" at 2101.11,-4182.53 h45
  text "6" at -7.78,-4338.9 h70
  text "5" at 2497.22,-4338.9 h70
  text "4" at 4996.21,-4338.9 h70
  text "3" at 7502.88,-4338.9 h70
  text "2" at 9992.22,-4338.9 h70
  text "1" at 12487.88,-4338.9 h70

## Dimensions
0,0 to -180.85,-175 on Drill Drawing
0,0 to -180.85,-175 on Drill Drawing
74.15,425 to -595,-250 on Top Assy TOP (M11)/Assy BOT (M10)
-180.85,3325 to -180.85,-175 on Drill Drawing
-180.85,3325 to 4619.15,3325 on Drill Drawing
4110.95,1343.98 to 5482.95,-99.02 on Drill Drawing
